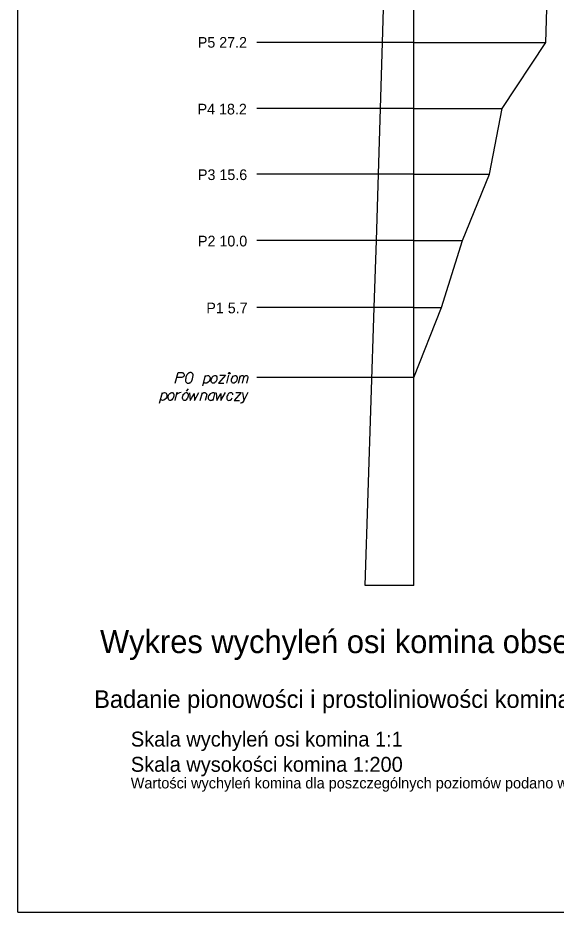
# Model space of a CAD drawing. Extents: x 138 to 6653, y -177 to 1520.
# Drawn here: x 169.1 to 180.2, y 2.29 to 20.71 of the extents above; entities that cross this region are included whole.
import ezdxf

# ---------------------------------------------------------------- set-up
doc = ezdxf.new("R2010")
doc.units = 0
for name, color, linetype in [('15 listopad 2008', 7, 'Continuous'), ('Opisy', 7, 'Continuous'), ('Ramka do drukowania', 7, 'Continuous'), ('Standart wykresów', 7, 'Continuous'), ('Wykresy 4 maj 2008', 7, 'Continuous')]:
    doc.layers.add(name, color=color, linetype=linetype)

msp = doc.modelspace()

# ---------------------------------------------------------------- linework, layer by layer
at = {"layer": '15 listopad 2008'}
msp.add_lwpolyline([(177.265, 13.297), (177.835, 14.742), (178.265, 16.118), (178.825, 17.485), (179.085, 18.843), (179.985, 20.202), (180.025, 21.593), (180.955, 22.995), (181.325, 23.989), (181.555, 24.969), (181.195, 25.428), (181.505, 25.945), (181.835, 26.413), (182.385, 26.981), (181.765, 27.507), (182.385, 27.694), (182.255, 28.392), (182.255, 28.755), (183.205, 29.012)], dxfattribs=at)
at = {"layer": 'Ramka do drukowania'}
for q in [(169.105, 31.985), (190.105, 2.285)]:
    msp.add_line((169.105, 2.285), q, dxfattribs=at)
at = {"layer": 'Standart wykresów'}
for p, q in [((177.265, 9.011), (177.265, 29.095)), ((176.618, 20.202), (176.663, 21.593)), ((177.265, 20.202), (174.028, 20.202)), ((176.576, 18.843), (176.618, 20.202)), ((177.265, 18.843), (174.028, 18.843)), ((176.534, 17.485), (176.576, 18.843)), ((177.265, 17.485), (174.028, 17.485)), ((176.491, 16.118), (176.534, 17.485)), ((177.265, 16.118), (174.028, 16.118)), ((176.447, 14.742), (176.491, 16.118)), ((177.265, 14.742), (174.028, 14.742)), ((176.259, 9.011), (176.447, 14.742)), ((177.265, 13.297), (174.028, 13.297)), ((177.265, 9.011), (176.259, 9.011))]:
    msp.add_line(p, q, dxfattribs=at)
for points in [[(172.349, 13.181), (172.408, 13.401), (172.483, 13.401), (172.493, 13.399), (172.498, 13.398), (172.509, 13.392), (172.515, 13.387), (172.521, 13.38), (172.526, 13.372), (172.529, 13.36), (172.531, 13.349), (172.529, 13.341), (172.528, 13.334), (172.524, 13.327), (172.521, 13.321), (172.515, 13.315), (172.509, 13.309), (172.503, 13.306), (172.495, 13.302), (172.486, 13.301), (172.382, 13.301)], [(172.664, 13.401), (172.661, 13.401), (172.651, 13.399), (172.644, 13.398), (172.638, 13.396), (172.63, 13.392), (172.619, 13.387), (172.611, 13.382), (172.602, 13.375), (172.597, 13.368), (172.592, 13.36), (172.587, 13.351), (172.581, 13.341), (172.578, 13.334), (172.574, 13.323), (172.569, 13.306), (172.564, 13.28), (172.561, 13.259), (172.561, 13.24), (172.562, 13.226), (172.569, 13.211), (172.574, 13.202), (172.583, 13.192), (172.593, 13.185), (172.599, 13.183), (172.609, 13.181), (172.618, 13.181), (172.632, 13.183), (172.644, 13.186), (172.652, 13.192), (172.664, 13.2), (172.67, 13.205), (172.677, 13.212), (172.682, 13.219), (172.685, 13.224), (172.689, 13.233), (172.69, 13.237), (172.694, 13.245), (172.697, 13.256), (172.701, 13.266), (172.703, 13.273), (172.704, 13.278), (172.706, 13.285), (172.709, 13.301), (172.711, 13.309), (172.713, 13.318), (172.715, 13.33), (172.716, 13.346), (172.716, 13.351), (172.715, 13.358), (172.713, 13.365), (172.708, 13.375), (172.703, 13.382), (172.697, 13.387), (172.69, 13.392), (172.684, 13.396), (172.678, 13.398), (172.673, 13.399), (172.664, 13.401)], [(172.916, 13.124), (172.974, 13.341)], [(172.969, 13.321), (172.987, 13.335), (173.013, 13.341), (173.033, 13.337), (173.047, 13.327), (173.058, 13.313), (173.065, 13.294), (173.066, 13.276), (173.063, 13.261), (173.058, 13.242), (173.044, 13.221), (173.026, 13.202), (173, 13.185), (172.978, 13.181), (172.957, 13.183), (172.935, 13.195)], [(173.163, 13.341), (173.175, 13.341), (173.189, 13.334), (173.203, 13.315), (173.205, 13.306), (173.207, 13.297), (173.207, 13.29), (173.207, 13.264), (173.201, 13.247), (173.193, 13.226), (173.182, 13.209), (173.165, 13.193), (173.149, 13.181), (173.123, 13.181), (173.113, 13.185), (173.103, 13.193), (173.097, 13.202), (173.091, 13.223), (173.091, 13.254), (173.094, 13.264), (173.101, 13.287), (173.108, 13.299), (173.111, 13.306), (173.129, 13.325), (173.146, 13.335), (173.163, 13.341)], [(173.267, 13.344), (173.38, 13.344), (173.236, 13.181), (173.347, 13.181)], [(173.409, 13.181), (173.454, 13.349)], [(173.458, 13.401), (173.466, 13.401), (173.472, 13.398), (173.477, 13.391), (173.477, 13.382), (173.472, 13.375), (173.466, 13.372), (173.458, 13.372), (173.453, 13.375), (173.447, 13.382), (173.447, 13.391), (173.453, 13.398), (173.458, 13.401)], [(173.579, 13.341), (173.591, 13.341), (173.605, 13.334), (173.619, 13.315), (173.621, 13.306), (173.622, 13.297), (173.622, 13.29), (173.622, 13.264), (173.617, 13.247), (173.608, 13.226), (173.598, 13.209), (173.581, 13.193), (173.565, 13.181), (173.539, 13.181), (173.529, 13.185), (173.518, 13.193), (173.513, 13.202), (173.506, 13.223), (173.506, 13.254), (173.51, 13.264), (173.517, 13.287), (173.524, 13.299), (173.527, 13.306), (173.544, 13.325), (173.562, 13.335), (173.579, 13.341)], [(173.652, 13.181), (173.692, 13.339)], [(173.681, 13.297), (173.69, 13.316), (173.699, 13.327), (173.709, 13.334), (173.719, 13.339), (173.726, 13.342), (173.737, 13.342), (173.74, 13.341), (173.747, 13.334), (173.754, 13.325), (173.759, 13.309), (173.761, 13.301), (173.77, 13.316), (173.78, 13.327), (173.79, 13.334), (173.801, 13.339), (173.809, 13.342), (173.818, 13.342), (173.825, 13.341), (173.83, 13.334), (173.835, 13.325), (173.841, 13.309), (173.842, 13.301), (173.813, 13.181)], [(173.731, 13.181), (173.761, 13.301)], [(172.026, 12.771), (172.085, 12.987)], [(172.08, 12.968), (172.097, 12.982), (172.123, 12.987), (172.144, 12.984), (172.158, 12.973), (172.168, 12.96), (172.175, 12.941), (172.177, 12.923), (172.173, 12.908), (172.168, 12.889), (172.154, 12.868), (172.137, 12.849), (172.111, 12.831), (172.088, 12.828), (172.068, 12.83), (172.045, 12.842)], [(172.274, 12.987), (172.286, 12.987), (172.3, 12.98), (172.314, 12.961), (172.315, 12.953), (172.317, 12.944), (172.317, 12.937), (172.317, 12.911), (172.312, 12.894), (172.303, 12.873), (172.293, 12.856), (172.275, 12.84), (172.26, 12.828), (172.234, 12.828), (172.223, 12.831), (172.213, 12.84), (172.208, 12.849), (172.201, 12.87), (172.201, 12.901), (172.204, 12.911), (172.211, 12.934), (172.218, 12.946), (172.222, 12.953), (172.239, 12.972), (172.256, 12.982), (172.274, 12.987)], [(172.346, 12.828), (172.39, 12.993)], [(172.379, 12.953), (172.388, 12.96), (172.407, 12.973), (172.428, 12.982), (172.443, 12.987), (172.468, 12.993)], [(172.57, 12.987), (172.582, 12.987), (172.596, 12.98), (172.61, 12.961), (172.611, 12.953), (172.613, 12.944), (172.613, 12.937), (172.613, 12.911), (172.608, 12.894), (172.599, 12.873), (172.589, 12.856), (172.572, 12.84), (172.556, 12.828), (172.53, 12.828), (172.52, 12.831), (172.509, 12.84), (172.504, 12.849), (172.497, 12.87), (172.497, 12.901), (172.501, 12.911), (172.508, 12.934), (172.514, 12.946), (172.518, 12.953), (172.535, 12.972), (172.553, 12.982), (172.57, 12.987)], [(172.613, 13.064), (172.57, 13.015)], [(172.643, 12.986), (172.656, 12.828), (172.74, 12.972), (172.741, 12.828), (172.833, 12.989)], [(172.863, 12.828), (172.906, 12.987)], [(172.896, 12.949), (172.901, 12.958), (172.908, 12.968), (172.913, 12.973), (172.92, 12.98), (172.927, 12.984), (172.935, 12.987), (172.944, 12.989), (172.951, 12.989), (172.96, 12.987), (172.967, 12.984), (172.973, 12.98), (172.98, 12.975), (172.987, 12.968), (172.991, 12.963), (172.994, 12.956), (172.998, 12.947), (172.967, 12.828)], [(173.157, 12.973), (173.145, 12.982), (173.116, 12.982), (173.098, 12.979), (173.067, 12.961), (173.041, 12.93), (173.029, 12.897), (173.027, 12.88), (173.029, 12.866), (173.034, 12.854), (173.044, 12.84), (173.057, 12.831), (173.076, 12.828), (173.09, 12.83), (173.103, 12.831), (173.122, 12.842)], [(173.161, 12.987), (173.119, 12.828)], [(173.19, 12.986), (173.204, 12.828), (173.287, 12.972), (173.289, 12.828), (173.381, 12.989)], [(173.533, 12.941), (173.531, 12.961), (173.523, 12.975), (173.512, 12.982), (173.491, 12.986), (173.472, 12.986), (173.448, 12.97), (173.429, 12.944), (173.415, 12.918), (173.41, 12.899), (173.41, 12.87), (173.412, 12.859), (173.419, 12.845), (173.434, 12.831), (173.452, 12.828), (173.471, 12.83), (173.481, 12.833), (173.504, 12.849), (173.521, 12.878)], [(173.594, 12.991), (173.706, 12.991), (173.562, 12.828), (173.673, 12.828)], [(173.846, 12.989), (173.758, 12.828), (173.73, 12.781), (173.723, 12.778), (173.715, 12.774), (173.698, 12.771), (173.691, 12.771)], [(173.736, 12.987), (173.758, 12.828)]]:
    msp.add_lwpolyline(points, dxfattribs=at)
at = {"layer": 'Wykresy 4 maj 2008'}
for p, q in [((177.265, 20.202), (179.985, 20.202)), ((177.265, 18.843), (179.085, 18.843)), ((177.265, 17.485), (178.825, 17.485)), ((177.265, 16.118), (178.265, 16.118)), ((177.265, 14.742), (177.835, 14.742))]:
    msp.add_line(p, q, dxfattribs=at)

# ---------------------------------------------------------------- texts
at = {"layer": 'Opisy'}
for s, height, p in [('Wykres wychyleń osi komina obserwowanych ze stanowiska 1000', 0.47516, (170.798, 7.621)), ('Badanie pionowości i prostoliniowości komina zakładu ceramicznego "Ceramika Stróże"', 0.36281, (170.678, 6.492)), ('Skala wychyleń osi komina 1:1', 0.30766, (171.433, 5.696)), ('Skala wysokości komina 1:200', 0.30766, (171.433, 5.176)), ('Wartości wychyleń komina dla poszczególnych poziomów podano w milimetrach', 0.22315, (171.43, 4.833))]:
    msp.add_text(s, height=height, dxfattribs=at).set_placement(p)
at = {"layer": 'Wykresy 4 maj 2008'}
for s, p in [('P5 27.2', (172.812, 20.092)), ('P4 18.2', (172.808, 18.717)), ('P3 15.6', (172.816, 17.366)), ('P2 10.0', (172.816, 15.999)), ('P1 5.7', (172.988, 14.621))]:
    msp.add_text(s, height=0.22, dxfattribs=at).set_placement(p)

doc.saveas('drawing.dxf')
